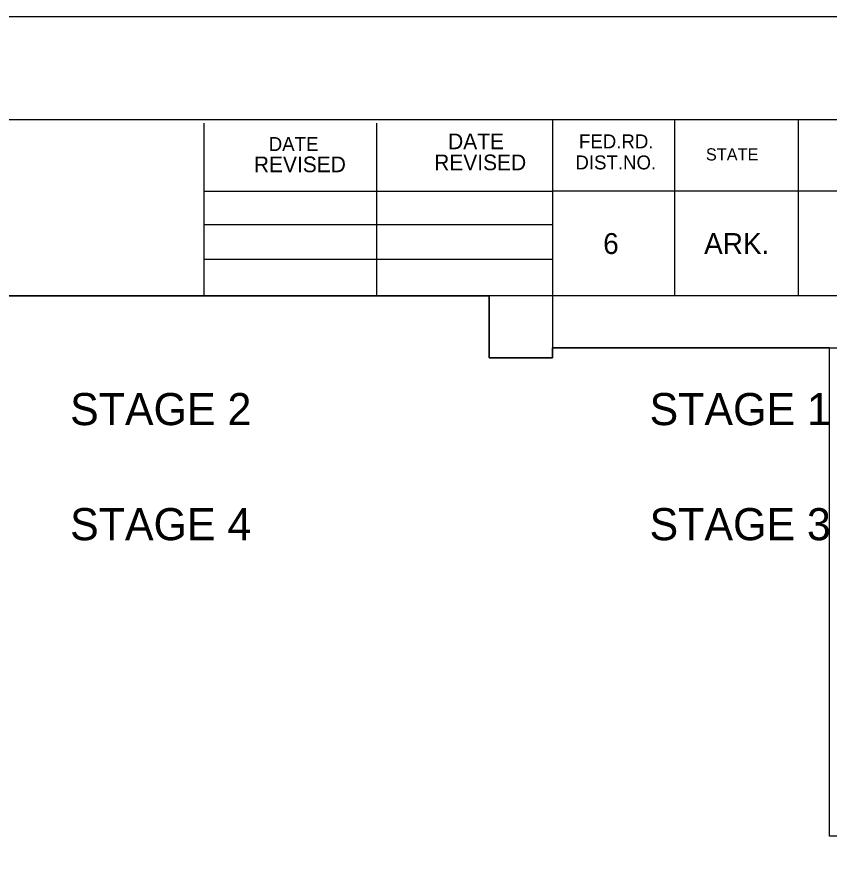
# Model space of a CAD drawing. Extents: x 0 to 1228740, y 0 to 152440.
# Drawn here: x 26.108 to 30.665, y 17.304 to 22 of the extents above; entities that cross this region are included whole.
import ezdxf

# ---------------------------------------------------------------- set-up
doc = ezdxf.new("R2010")
doc.units = 0
for name, color, linetype in [('R_Border', 7, 'Continuous'), ('R_No Plot', 7, 'Continuous'), ('R_XS_EARTHWORK_STAGE1', 7, 'Continuous'), ('R_XS_EARTHWORK_STAGE2', 7, 'Continuous'), ('R_XS_EARTHWORK_STAGE3', 7, 'Continuous'), ('R_XS_EARTHWORK_STAGE4', 7, 'Continuous')]:
    doc.layers.add(name, color=color, linetype=linetype)

msp = doc.modelspace()

# ---------------------------------------------------------------- linework, layer by layer
at = {"layer": 'R_Border'}
for p, q in [((1.516, 21.4232), (33.4231, 21.4232)), ((29.1131, 21.4232), (29.1131, 20.1432)), ((29.7971, 21.4232), (29.7971, 20.4352)), ((30.4911, 21.4232), (30.4911, 20.4352)), ((27.1591, 20.4352), (27.1591, 21.4032)), ((28.1271, 20.4352), (28.1271, 21.4032)), ((27.1591, 21.0212), (29.1131, 21.0212)), ((33.4231, 21.0212), (29.1131, 21.0212)), ((27.1591, 20.8352), (29.1131, 20.8352)), ((27.1591, 20.6412), (29.1131, 20.6412)), ((33.4231, 20.4352), (27.1591, 20.4352)), ((29.1131, 20.1432), (33.4231, 20.1432))]:
    msp.add_line(p, q, dxfattribs=at)
msp.add_lwpolyline([(33.9999, 22), (0, 22), (0, 0), (33.9999, 0)], close=True, dxfattribs=at)
at = {"layer": 'R_No Plot'}
msp.add_lwpolyline([(33.4231, 17.4052), (33.4231, 0.5768), (1.516, 0.5768), (1.516, 21.4232), (20.2672, 21.4232), (20.2672, 20.4352), (28.7566, 20.4351), (28.7566, 20.0873), (29.1132, 20.0873), (29.1131, 20.1432), (30.6665, 20.1432)], dxfattribs=at)
msp.add_lwpolyline([(20.2672, 21.4232), (1.516, 21.4232), (1.516, 10.8708), (33.4231, 10.8708), (33.4231, 17.4052), (30.6665, 17.4052), (30.6665, 20.1432), (29.1132, 20.1432), (29.1132, 20.0873), (28.7566, 20.0873), (28.7566, 20.4351), (20.2672, 20.4351)], close=True, dxfattribs=at)

# ---------------------------------------------------------------- texts
at = {"layer": 'R_Border'}
for s, height, p in [('DATE', 0.07819, (27.5209, 21.2472)), ('DATE', 0.08792, (28.5269, 21.2572)), ('FED.RD.', 0.07819, (29.2609, 21.262)), ('REVISED', 0.08792, (28.4489, 21.1392)), ('STATE', 0.0684, (29.9729, 21.194)), ('REVISED', 0.08792, (27.4376, 21.1282)), ('DIST.NO.', 0.07819, (29.2409, 21.144)), ('6', 0.1172, (29.3969, 20.6695)), ('ARK.', 0.11723, (29.9629, 20.6695))]:
    msp.add_text(s, height=height, dxfattribs=at).set_placement(p)
at = {"layer": 'R_XS_EARTHWORK_STAGE1'}
msp.add_text('STAGE 1', height=0.18, dxfattribs=at).set_placement((29.657, 19.71))
at = {"layer": 'R_XS_EARTHWORK_STAGE2'}
msp.add_text('STAGE 2', height=0.18, dxfattribs=at).set_placement((26.407, 19.71))
at = {"layer": 'R_XS_EARTHWORK_STAGE3'}
msp.add_text('STAGE 3', height=0.18, dxfattribs=at).set_placement((29.657, 19.0647))
at = {"layer": 'R_XS_EARTHWORK_STAGE4'}
msp.add_text('STAGE 4', height=0.18, dxfattribs=at).set_placement((26.407, 19.0647))

doc.saveas('drawing.dxf')
